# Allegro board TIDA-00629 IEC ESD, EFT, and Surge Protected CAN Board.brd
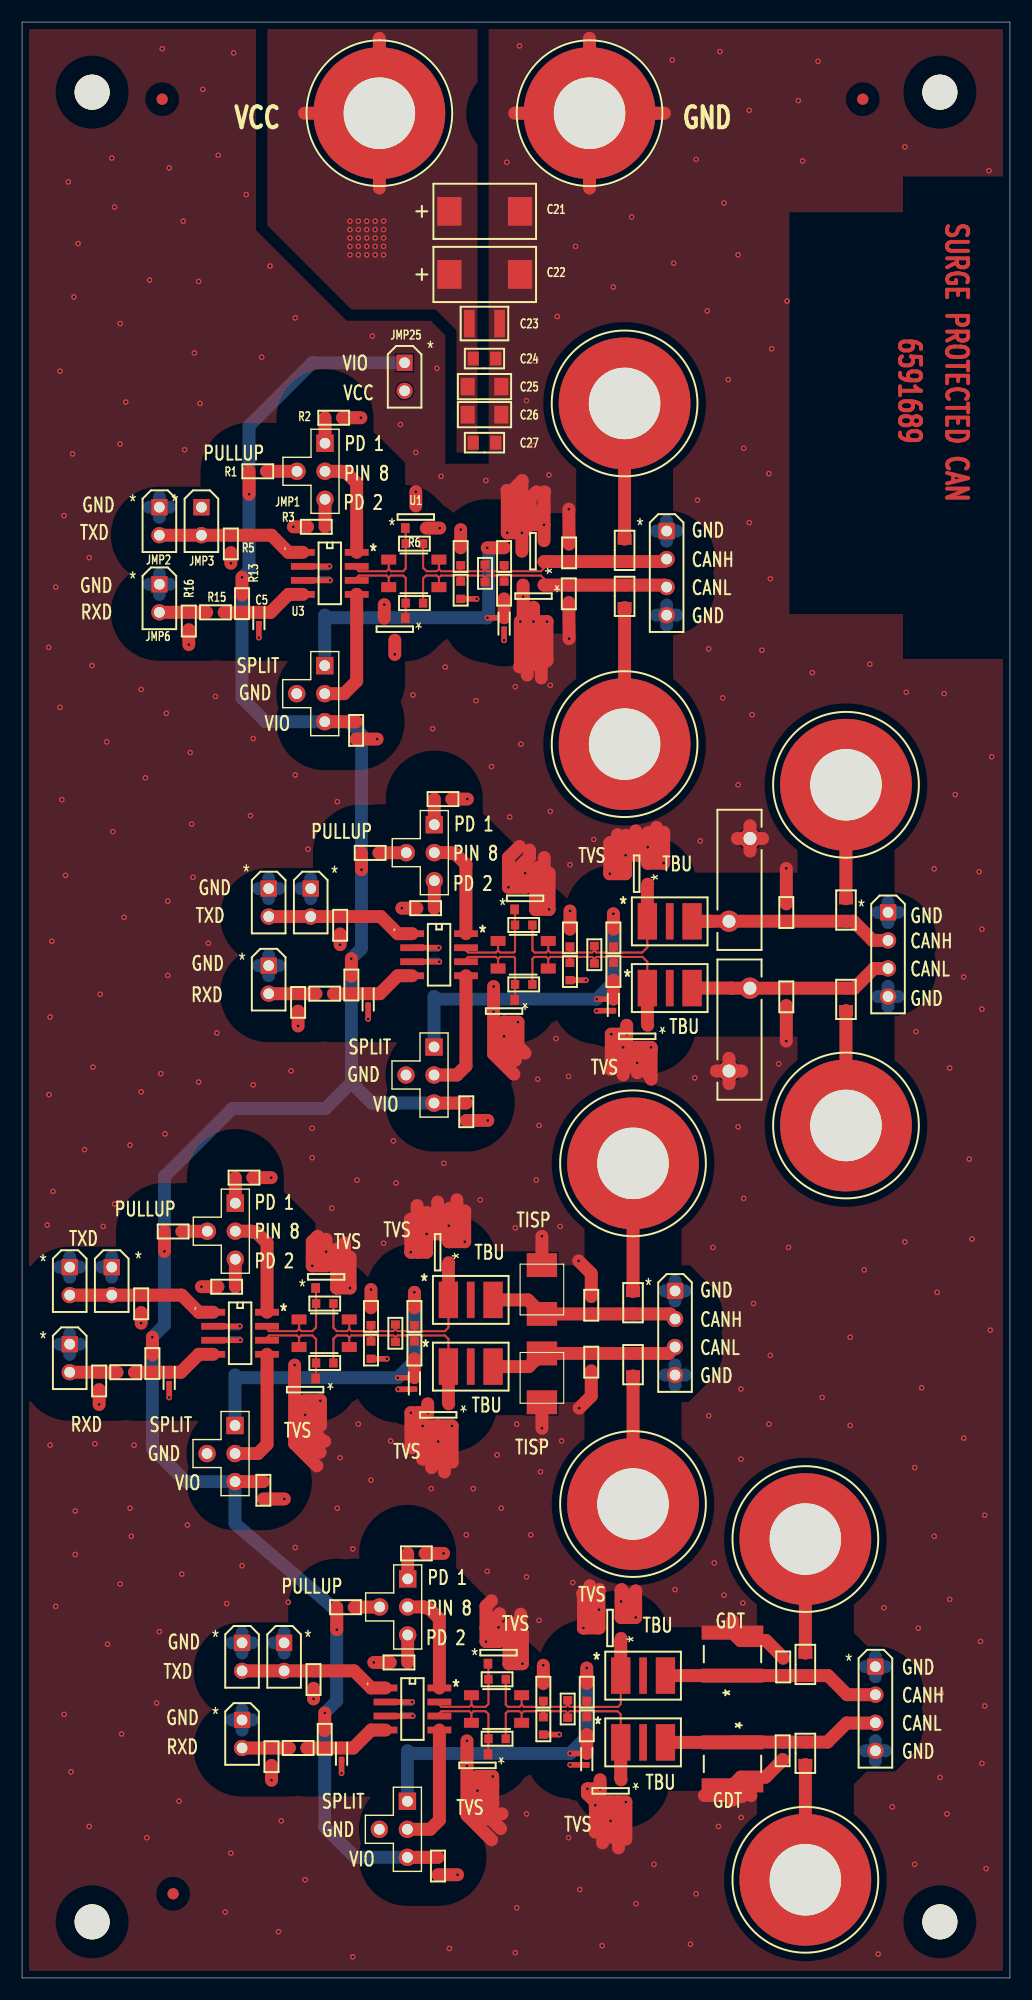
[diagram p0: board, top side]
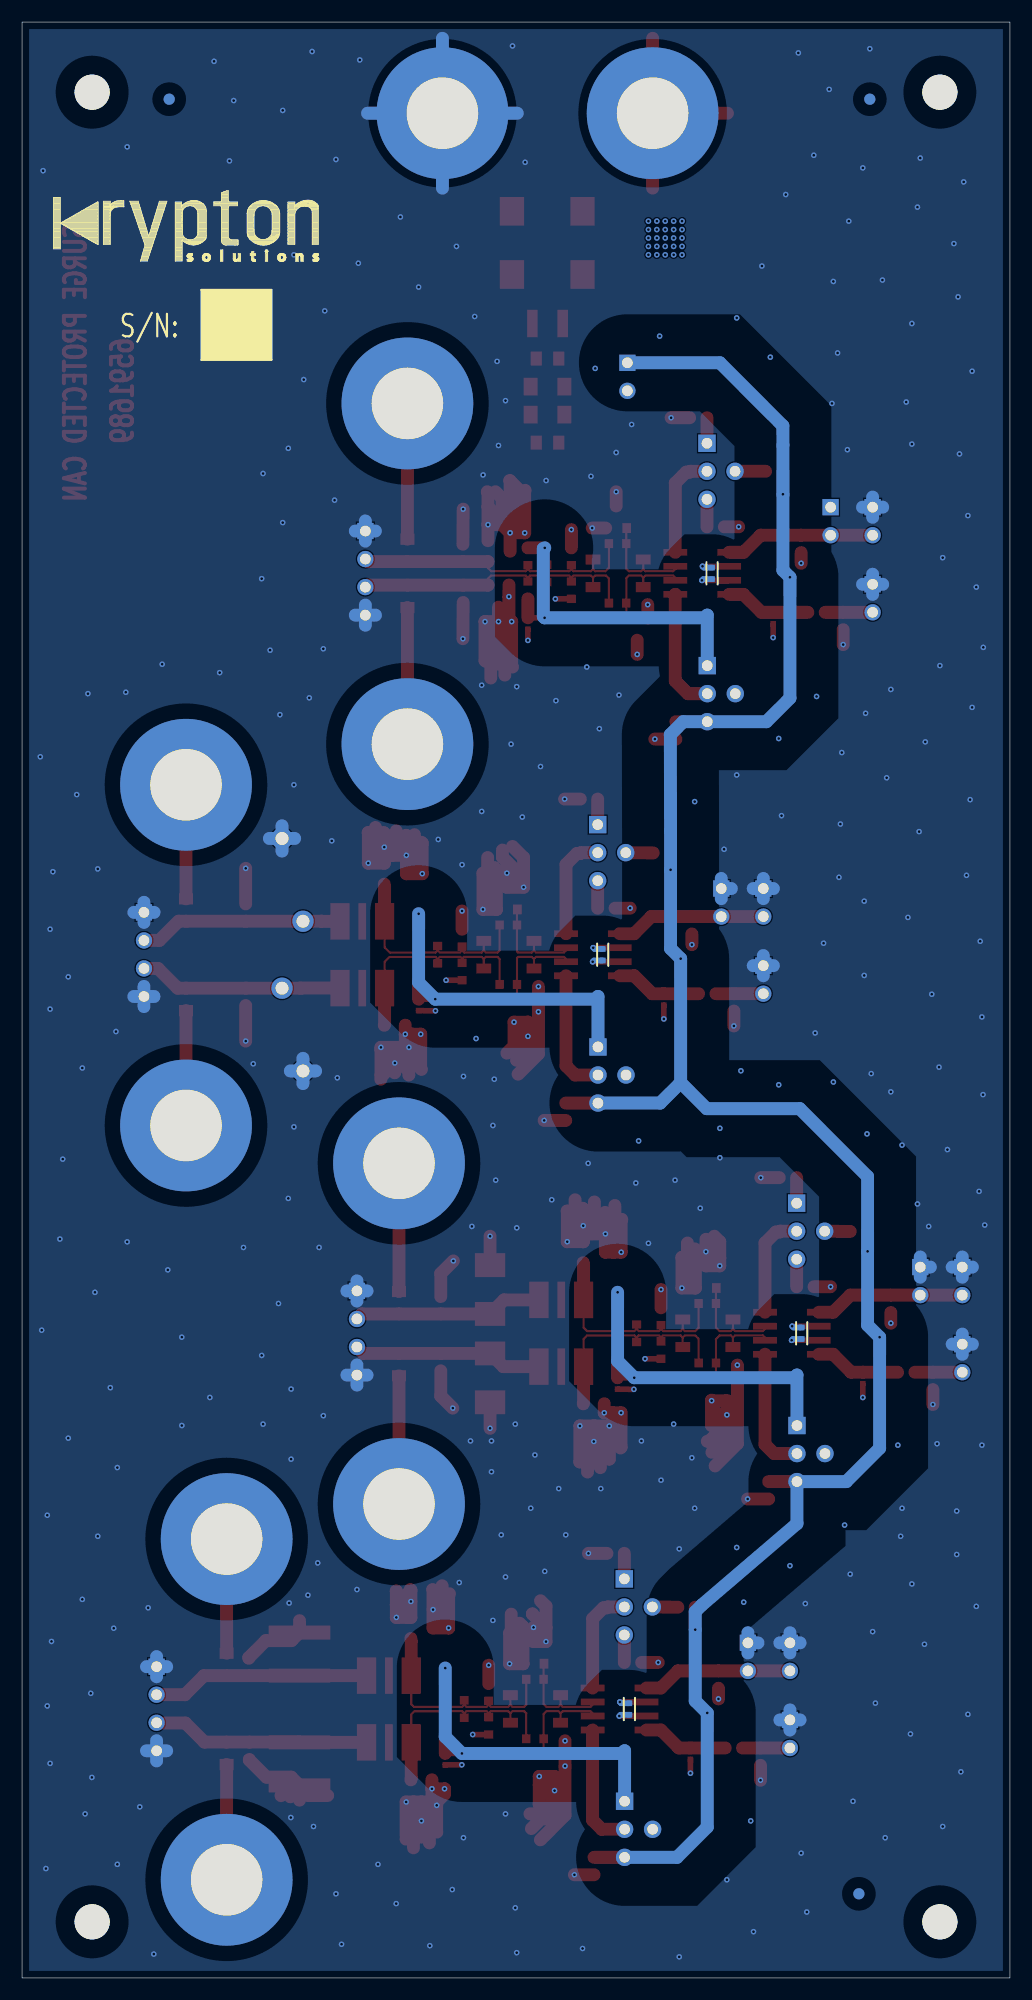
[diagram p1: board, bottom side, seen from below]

Outline 89.53 x 177.16 mm; copper layers: TOP, L2_GND, L3_PWR, BOTTOM. Coordinates in mm from the lower left corner of the outline.
Outline path: 0,177.16 89.53,177.16 89.53,0 0,0 0,177.16

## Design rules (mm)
net group DIFFPAIR0: nets RXD1 TXD1
net group DIFFPAIR1: nets CANH1 CANL1
net group DIFFPAIR2: nets RXD2 TXD2
net group DIFFPAIR3: nets CANH2 CANL2
net group DIFFPAIR4: nets RXD3 TXD3
net group DIFFPAIR5: nets CANH3 CANL3
net group DIFFPAIR6: nets RXD4 TXD4
net group DIFFPAIR7: nets CANH4 CANL4
net group DIFFPAIR8: nets CANH_4 CANL_4
net group DIFFPAIR9: nets CANH_1 CANL_1
net group DIFFPAIR10: nets CANH_2 CANL_2
net group DIFFPAIR11: nets CANH_3 CANL_3

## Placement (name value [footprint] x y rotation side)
C1  68pF  [0603]  49.58 129.08 90 top
C2  0.1uF  [0402]  27 127.23 90 bottom
C3  4.7nF_DNI  [0402]  43.69 122.68 270 top
C4  68pF  [0603]  49.56 125.37 270 top
C5  15pF_DNI  [0402]  21.46 123.18 270 top
C6  68pF  [0603]  69.27 96.5 90 top
C7  0.1uF  [0402]  36.91 92.68 90 bottom
C8  4.7nF_DNI  [0402]  53.59 88.14 270 top
C9  68pF  [0603]  69.27 88.87 270 top
C10  15pF_DNI  [0402]  31.37 88.63 270 top
C11  68pF  [0603]  51.59 60.93 90 top
C12  0.1uF  [0402]  18.87 58.39 90 bottom
C13  4.7nF_DNI  [0402]  35.56 53.85 270 top
C14  68pF  [0603]  51.59 55.78 270 top
C15  15pF_DNI  [0402]  13.34 54.34 270 top
C16  68pF  [0603]  68.99 28.17 90 top
C17  0.1uF  [0402]  34.49 24.36 90 bottom
C18  4.7nF_DNI  [0402]  51.18 19.81 270 top
C19  15pF_DNI  [0402]  28.96 20.31 270 top
C20  68pF  [0603]  68.94 20.57 270 top
C21  47uF  [7343]  38.73 160.02 0 top
C22  22uF  [7343]  38.73 154.31 0 top
C23  68uF  [1210]  41.91 149.86 0 top
C24  10uF  [0805]  41.91 146.69 0 top
C25  1uF  [1206]  41.91 144.15 0 top
C26  0.1uF  [1206]  41.91 141.6 0 top
C27  0.01uF  [0805]  41.91 139.06 0 top
C28  0.01uF  [0603]  30.28 113 90 top
C29  0.01uF  [0603]  40.26 78.46 90 top
C30  0.01uF  [0603]  21.87 44.17 90 top
C31  0.01uF  [0603]  37.69 10.13 90 top
JMP1  -  [BERG2X3TEE]  27.46 139.01 270 top
JMP2  -  [HDR_THVT_1X2_100]  12.45 133.22 0 top
JMP3  -  [HDR_THVT_1X2_100]  16.26 133.22 0 top
JMP4  -  [HDR_THVT_1X4_100]  58.42 131.06 0 top
JMP5  -  [BERG2X3TEE]  27.43 118.87 270 top
JMP6  -  [HDR_THVT_1X2_100]  12.45 126.24 0 top
JMP7  -  [BERG2X3TEE]  37.36 104.47 270 top
JMP8  -  [HDR_THVT_1X2_100]  22.35 98.68 0 top
JMP9  -  [HDR_THVT_1X2_100]  26.16 98.68 0 top
JMP10  -  [HDR_THVT_1X4_100]  78.49 96.52 0 top
JMP11  -  [BERG2X3TEE]  37.34 84.33 270 top
JMP12  -  [HDR_THVT_1X2_100]  22.35 91.69 0 top
JMP13  -  [BERG2X3TEE]  19.33 70.18 270 top
JMP14  -  [HDR_THVT_1X2_100]  4.32 64.39 0 top
JMP15  -  [HDR_THVT_1X2_100]  8.13 64.39 0 top
JMP16  -  [HDR_THVT_1X4_100]  59.18 62.23 0 top
JMP17  -  [BERG2X3TEE]  19.3 50.04 270 top
JMP18  -  [HDR_THVT_1X2_100]  4.32 57.4 0 top
JMP19  -  [BERG2X3TEE]  34.95 36.14 270 top
JMP20  -  [HDR_THVT_1X2_100]  19.94 30.35 0 top
JMP21  -  [HDR_THVT_1X2_100]  23.75 30.35 0 top
JMP22  -  [HDR_THVT_1X4_100]  77.34 28.19 0 top
JMP23  -  [BERG2X3TEE]  34.92 16 270 top
JMP24  -  [HDR_THVT_1X2_100]  19.94 23.37 0 top
JMP25  2 Pin Berg Jumper  [HDR_THVT_1X2_100]  34.67 146.3 0 top
L1  ACT45B Choke  [IND_ACT45B_SMT_4P5X3P2MM]  35.51 127.23 0 top
L2  ACT45B Choke  [IND_ACT45B_SMT_4P5X3P2MM]  45.42 92.68 0 top
L3  ACT45B Choke  [IND_ACT45B_SMT_4P5X3P2MM]  27.38 58.39 0 top
L4  ACT45B Choke  [IND_ACT45B_SMT_4P5X3P2MM]  43 24.36 0 top
NOREF  -  []  89.53 0 90 top
NOREF#2  -  [unnamed#2]  76.2 170.18 0 top
NOREF#3  -  []  88.9 38.1 0 top
NOREF#4  -  [unnamed#2]  83.19 170.81 0 top
NOREF#5  -  []  70.97 158.14 270 top
NOREF#6  -  [unnamed#2]  12.7 170.18 0 top
NOREF#7  -  [unnamed#2]  6.35 170.81 0 top
NOREF#8  -  [unnamed#2]  83.19 5.08 0 top
NOREF#9  -  []  0 177.16 0 top
NOREF#10  -  []  0 0 0 top
NOREF#11  -  []  -3.81 -69.85 0 top
NOREF#12  -  [unnamed#2]  6.35 5.08 0 top
NOREF#13  -  [unnamed#2]  13.69 7.62 0 top
NOREF#14  -  [unnamed#2]  12.7 170.18 180 bottom
NOREF#15  -  [unnamed#2]  76.2 170.18 180 bottom
NOREF#16  -  []  78.23 137.92 180 bottom
NOREF#17  -  []  86.74 155.45 180 bottom
NOREF#18  -  []  80.26 149.73 180 bottom
NOREF#19  -  [unnamed#2]  13.69 7.62 180 bottom
P1  CANH SURGE INPUT  [JACK_THVT_BANANA_500DIA]  54.61 142.62 0 top
P2  CANL SURGE INPUT  [JACK_THVT_BANANA_500DIA]  54.61 111.76 0 top
P3  CANH SURGE INPUT  [JACK_THVT_BANANA_500DIA]  74.68 108.08 0 top
P4  CANL SURGE INPUT  [JACK_THVT_BANANA_500DIA]  74.68 77.22 0 top
P5  CANH SURGE INPUT  [JACK_THVT_BANANA_500DIA]  55.37 73.79 0 top
P6  CANL SURGE INPUT  [JACK_THVT_BANANA_500DIA]  55.37 42.93 0 top
P7  CANH SURGE INPUT  [JACK_THVT_BANANA_500DIA]  70.99 39.75 0 top
P8  CANL SURGE INPUT  [JACK_THVT_BANANA_500DIA]  70.99 8.89 0 top
P9  GND  [JACK_THVT_BANANA_500DIA]  51.44 168.91 0 top
P10  VCC  [JACK_THVT_BANANA_500DIA]  32.38 168.91 0 top
R1  4.7k  [0603]  21.36 136.47 0 top
R2  0  [0603]  28.24 141.33 0 top
R3  10k  [0603]  26.67 131.44 180 top
R4  0  [0805]  54.61 129.31 270 top
R5  49.9  [0603]  18.92 129.9 270 top
R6  0_DNI  [0603]  35.56 129.92 0 top
R7  49.9_DNI  [0603]  39.75 128.75 90 top
R8  60.4_DNI  [0603]  43.69 128.75 90 top
R9  120  [0603]  41.96 127.23 270 top
R10  0_DNI  [0603]  35.56 124.54 0 top
R11  60.4_DNI  [0603]  43.69 125.7 90 top
R12  49.9_DNI  [0603]  39.75 125.7 270 top
R13  10k_DNI  [0603]  19.94 124.49 90 top
R14  0  [0805]  54.61 125.15 270 top
R15  453  [0603]  17.53 123.7 0 top
R16  49.9  [0603]  15.11 122.91 90 top
R17  4.7k  [0603]  31.55 101.9 0 top
R18  0  [0805]  74.68 96.73 270 top
R19  0  [0603]  38.15 106.78 0 top
R20  10k  [0603]  36.58 96.9 180 top
R21  49.9  [0603]  28.83 95.35 270 top
R22  0_DNI  [0603]  45.47 95.38 0 top
R23  49.9_DNI  [0603]  49.66 94.21 90 top
R24  60_DNI  [0603]  53.59 94.21 90 top
R25  120  [0603]  51.87 92.68 270 top
R26  0_DNI  [0603]  45.47 89.99 0 top
R27  60_DNI  [0603]  53.59 91.16 90 top
R28  49.9_DNI  [0603]  49.66 91.16 270 top
R29  10k_DNI  [0603]  29.84 89.94 90 top
R30  453  [0603]  27.43 89.15 0 top
R31  49.9  [0603]  25.02 88.37 90 top
R32  0  [0805]  74.68 88.64 270 top
R33  4.7k  [0603]  13.69 67.61 0 top
R34  0  [0805]  55.37 61.16 270 top
R35  0  [0603]  20.12 72.49 0 top
R36  10k  [0603]  18.54 62.61 180 top
R37  49.9  [0603]  10.79 61.06 270 top
R38  0_DNI  [0603]  27.43 61.09 0 top
R39  49.9_DNI  [0603]  31.62 59.92 90 top
R40  60_DNI  [0603]  35.56 59.92 90 top
R41  120  [0603]  33.83 58.39 270 top
R42  0_DNI  [0603]  27.43 55.7 0 top
R43  60_DNI  [0603]  35.56 56.87 90 top
R44  49.9_DNI  [0603]  31.62 56.87 270 top
R45  10k_DNI  [0603]  11.81 55.65 90 top
R46  453  [0603]  9.4 54.86 0 top
R47  49.9  [0603]  6.99 54.08 90 top
R48  0  [0805]  55.37 55.55 270 top
R49  4.7k  [0603]  29.31 33.58 0 top
R50  0  [0805]  70.99 28.4 270 top
R51  0  [0603]  35.74 38.46 0 top
R52  10k  [0603]  34.16 28.57 180 top
R53  49.9  [0603]  26.42 27.03 270 top
R54  0_DNI  [0603]  43.05 27.05 0 top
R55  49.9_DNI  [0603]  47.24 25.88 90 top
R56  60_DNI  [0603]  51.18 25.88 90 top
R57  120  [0603]  49.45 24.36 270 top
R58  0_DNI  [0603]  43.05 21.67 0 top
R59  60_DNI  [0603]  51.18 22.83 90 top
R60  49.9_DNI  [0603]  47.24 22.83 270 top
R61  10k_DNI  [0603]  27.43 21.62 90 top
R62  453  [0603]  25.02 20.83 0 top
R63  49.9  [0603]  22.61 20.04 90 top
R64  0  [0805]  70.99 20.35 270 top
U1  T12LC  [SOT_23_321]  35.69 132.33 0 top
U2  T12LC  [SOT_23_321]  46.3 129.24 90 top
U3  SN65HVD1040  [SOIC8_157X197_50]  27.89 127.23 0 top
U4  T12LC  [SOT_23_321]  33.78 122.17 180 top
U5  T12LC  [SOT_23_321]  46.35 125.17 180 top
U6  T12LC  [SOT_23_321]  55.7 100.03 90 top
U7  T12LC  [SOT_23_321]  45.59 97.79 0 top
U8  TBU-CA085-200-WH  [DFN_3_157X256]  58.7 95.71 0 top
U9  MOV-10D201K  [VAR_DISC_3P8X12P5MM]  65.02 99.47 90 top
U10  SN65HVD1040  [SOIC8_157X197_50]  37.8 92.68 0 top
U11  MOV-10D201K  [VAR_DISC_3P8X12P5MM]  65.02 85.9 90 top
U12  T12LC  [SOT_23_321]  43.69 87.58 180 top
U13  TBU-CA085-200-WH  [DFN_3_157X256]  58.7 89.66 0 top
U14  T12LC  [SOT_23_321]  55.75 85.29 180 top
U15  T12LC  [SOT_23_321]  37.67 65.74 90 top
U16  T12LC  [SOT_23_321]  27.56 63.5 0 top
U17  TBU-CA085-200-WH  [DFN_3_157X256]  40.67 61.42 0 top
U18  TISP4240M3BJR-S  [DO-214AA]  47.12 62.36 90 top
U19  SN65HVD1040  [SOIC8_157X197_50]  19.76 58.39 0 top
U20  TISP4240M3BJR-S  [DO-214AA]  47.12 54.36 90 top
U21  TBU-CA085-200-WH  [DFN_3_157X256]  40.67 55.37 0 top
U22  T12LC  [SOT_23_321]  25.65 53.29 180 top
U23  T12LC  [SOT_23_321]  37.72 51 180 top
U24  T12LC  [SOT_23_321]  53.29 31.7 90 top
U25  TBU-CA085-200-WH  [DFN_3_157X256]  56.29 27.38 0 top
U26  T12LC  [SOT_23_321]  43.18 29.46 0 top
U27  2031-42T-SM-RPLF  [GDT_SM_2031-XXT]  64.39 29.33 90 top
U28  SN65HVD1040  [SOIC8_157X197_50]  35.38 24.36 0 top
U29  2031-42T-SM-RPLF  [GDT_SM_2031-XXT]  64.39 19.39 270 top
U30  T12LC  [SOT_23_321]  41.27 19.25 180 top
U31  TBU-CA085-200-WH  [DFN_3_157X256]  56.29 21.34 0 top
U32  T12LC  [SOT_23_321]  53.34 16.94 180 top

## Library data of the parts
C1 C4 C6 C9 C11 C14 C16 C20 C24 = CAP NP
C2 C3 C5 C7 C8 C10 C12 C13 C15 C17-C19 C28-C31 = cc0402
C21 C22 = c7343
C23 C25 = NPCap1206_1.0uf
C26 = NPCap1206_0.1uf
C27 = NPCap0805_0.01uf
JMP1 JMP5 JMP7 JMP11 JMP13 JMP17 JMP19 JMP23 = 4 Pin-T Berg Jumper
JMP2 JMP3 JMP6 JMP8 JMP9 JMP12 JMP14 JMP15 JMP18 JMP20 JMP21 JMP24 JMP25 = 2 Pin Berg Jumper
JMP4 JMP10 JMP16 JMP22 = 4 Pin Berg Jumper Stagard Side
L1-L4 = ACT45B Choke
P1-P10 = Banana-Jack
R1-R64 = r0603
U1 U2 U4-U7 U12 U14-U16 U22-U24 U26 U30 U32 = CDSOT23-T12LC_0
U3 U10 U19 U28 = SN65HVD1040
U8 U13 U17 U21 U25 U31 = TBU-CA085-200-WH_0
U9 U11 = MOV-10D201K
U18 U20 = TISP4240M3BJR-S
U27 U29 = 2031-42T-SM-RPLF

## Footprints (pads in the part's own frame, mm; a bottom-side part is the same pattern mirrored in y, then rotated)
0402
  rect 0.508x0.508 smd: 1(-0.521,0) 2(0.521,0)
0603
  rect 0.762x0.813 smd: 1(-0.787,0) 2(0.787,0)
0805
  rect 1.016x1.27 smd: 1(-1.016,0) 2(1.016,0)
1206
  rect 1.27x1.6 smd: 1(-1.524,0) 2(1.524,0)
1210
  rect 0.965x2.489 smd: 1(-1.372,0) 2(1.372,0)
7343
  rect 2.2x2.601 smd: 1(0,0) 2(6.4,0)
BERG2X3TEE
  rect 1.575x1.575 hole 0.965: 1(0,0)
  round 1.575 hole 0.965: 2(2.54,0) 3(5.08,0) 4(2.54,-2.54)
DFN_3_157X256
  rect 1.75x3.3 smd: 1(-2.025,0) 3(2.025,0)
  rect 0.7x3.3 smd: 2(0,0)
DO-214AA
  rect 2.16x2.75 smd: 1(-2.21,0) 2(2.21,0)
GDT_SM_2031-XXT
  rect 1.27x5.588 smd: 1(-1.95,0) 2(1.95,0)
HDR_THVT_1X2_100
  rect 1.473x1.473 hole 0.965: 1(0,0)
  round 1.473 hole 0.965: 2(0,-2.54)
HDR_THVT_1X4_100
  rect 1.473x1.473 hole 0.965: 1(0,0)
  round 1.473 hole 0.965: 2(0,-2.54) 3(0,-5.08) 4(0,-7.62)
IND_ACT45B_SMT_4P5X3P2MM
  rect 1.35x0.9 smd: 1(-2.275,1.25) 2(-2.275,-1.25) 3(2.275,-1.25) 4(2.275,1.25)
JACK_THVT_BANANA_500DIA
  round 11.938 hole 6.477: 1(0,0)
SOIC8_157X197_50
  rect 2.159x0.61 smd: 1(-2.44,1.905) 2(-2.44,0.635) 3(-2.44,-0.635) 4(-2.44,-1.905) 5(2.44,-1.905) 6(2.44,-0.635) 7(2.44,0.635) 8(2.44,1.905)
SOT_23_321
  rect 0.787x0.889 smd: 1(-0.953,-1.003) 2(0.953,-1.003) 3(0,1.003)
unnamed#2
  round 1.016 smd: (0,0)
VAR_DISC_3P8X12P5MM
  round 1.93 hole 1.168: 1(-3.75,0.95) 2(3.75,-0.95)

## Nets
GND: C1.2 C2.2 C3.2 C4.2 C5.2 C6.2 C7.2 C8.2 C9.2 C10.2 C11.2 C12.2 C13.2 C14.2 C15.2 C16.2 C17.2 C18.2 C19.2 C20.2 C21.2 C22.2 C23.2 C24.2 C25.2 C26.2 C27.2 C28.1 C29.1 C30.1 C31.1 JMP2.1 JMP3.1 JMP4.1 JMP4.4 JMP5.4 JMP6.1 JMP8.1 JMP9.1 JMP10.1 JMP10.4 JMP11.4 JMP12.1 JMP14.1 JMP15.1 JMP16.1 JMP16.4 JMP17.4 JMP18.1 JMP20.1 JMP21.1 JMP22.1 JMP22.4 JMP23.4 JMP24.1 P9.1(V) R2.2 R3.2 R5.2 R7.2 R12.2 R16.1 R19.2 R20.2 R21.2 R23.2 R28.2 R31.1 R35.2 R36.2 R37.2 R39.2 R44.2 R47.1 R51.2 R52.2 R53.2 R55.2 R60.2 R63.1 U1.2(GND2) U1.3(GND1) U2.2(GND2) U2.3(GND1) U3.2(GND) U4.2(GND2) U4.3(GND1) U5.2(GND2) U5.3(GND1) U6.2(GND2) U6.3(GND1) U7.2(GND2) U7.3(GND1) U9.2 U10.2(GND) U11.1 U12.2(GND2) U12.3(GND1) U14.2(GND2) U14.3(GND1) U15.2(GND2) U15.3(GND1) U16.2(GND2) U16.3(GND1) U18.2(GND) U19.2(GND) U20.1(SIGNAL) U22.2(GND2) U22.3(GND1) U23.2(GND2) U23.3(GND1) U24.2(GND2) U24.3(GND1) U26.2(GND2) U26.3(GND1) U27.2(IN2) U28.2(GND) U29.2(IN2) U30.2(GND2) U30.3(GND1) U32.2(GND2) U32.3(GND1)
VCC: C2.1 C7.1 C12.1 C17.1 C21.1 C22.1 C23.1 C24.1 C25.1 C26.1 C27.1 JMP25.2 P10.1(V) U3.3(VCC) U10.3(VCC) U19.3(VCC) U28.3(VCC)
CANH1: L1.1 R6.1 U1.1(SIG) U3.7(CANH)
CANH2: L2.1 R22.1 U7.1(SIG) U10.7(CANH)
CANH3: L3.1 R38.1 U16.1(SIG) U19.7(CANH)
CANH4: L4.1 R54.1 U26.1(SIG) U28.7(CANH)
CANH_1: C1.1 JMP4.2 L1.4 R4.2 R6.2 R7.1 R8.1 R9.1 U2.1(SIG)
CANH_2: L2.4 R22.2 R23.1 R24.1 R25.1 U6.1(SIG) U8.1(IN)
CANH_2A: C6.1 JMP10.2 R18.2 U8.3(OUT1) U9.1
CANH_3: L3.4 R38.2 R39.1 R40.1 R41.1 U15.1(SIG) U17.1(IN)
CANH_3A: C11.1 JMP16.2 R34.2 U17.3(OUT1) U18.1(SIGNAL)
CANH_4: L4.4 R54.2 R55.1 R56.1 R57.1 U24.1(SIG) U25.1(IN)
CANH_4A: C16.1 JMP22.2 R50.2 U25.3(OUT1) U27.1(IN1)
CANH_SURGE1: P1.1(V) R4.1
CANH_SURGE2: P3.1(V) R18.1
CANH_SURGE3: P5.1(V) R34.1
CANH_SURGE4: P7.1(V) R50.1
CANL1: L1.2 R10.1 U3.6(CANL) U4.1(SIG)
CANL2: L2.2 R26.1 U10.6(CANL) U12.1(SIG)
CANL3: L3.2 R42.1 U19.6(CANL) U22.1(SIG)
CANL4: L4.2 R58.1 U28.6(CANL) U30.1(SIG)
CANL_1: C4.1 JMP4.3 L1.3 R9.2 R10.2 R11.2 R12.1 R14.1 U5.1(SIG)
CANL_2: L2.3 R25.2 R26.2 R27.2 R28.1 U13.1(IN) U14.1(SIG)
CANL_2A: C9.1 JMP10.3 R32.1 U11.2 U13.3(OUT1)
CANL_3: L3.3 R41.2 R42.2 R43.2 R44.1 U21.1(IN) U23.1(SIG)
CANL_3A: C14.1 JMP16.3 R48.1 U20.2(GND) U21.3(OUT1)
CANL_4: L4.3 R57.2 R58.2 R59.2 R60.1 U31.1(IN) U32.1(SIG)
CANL_4A: C20.1 JMP22.3 R64.1 U29.1(IN1) U31.3(OUT1)
CANL_SURGE1: P2.1(V) R14.2
CANL_SURGE2: P4.1(V) R32.2
CANL_SURGE3: P6.1(V) R48.2
CANL_SURGE4: P8.1(V) R64.2
PD1: JMP1.1 R2.1
PD2: JMP7.1 R19.1
PD3: JMP13.1 R35.1
PD4: JMP19.1 R51.1
PD_SC1: JMP1.3 R3.1
PD_SC2: JMP7.3 R20.1
PD_SC3: JMP13.3 R36.1
PD_SC4: JMP19.3 R52.1
PU1: JMP1.4 R1.2
PU2: JMP7.4 R17.2
PU3: JMP13.4 R33.2
PU4: JMP19.4 R49.2
RXD1: C5.1 R13.1 R15.2 U3.4(RXD)
RXD2: C10.1 R29.1 R30.2 U10.4(RXD)
RXD3: C15.1 R45.1 R46.2 U19.4(RXD)
RXD4: C19.1 R61.1 R62.2 U28.4(RXD)
RXD_SD1: JMP6.2 R15.1 R16.2
RXD_SD2: JMP12.2 R30.1 R31.2
RXD_SD3: JMP18.2 R46.1 R47.2
RXD_SD4: JMP24.2 R62.1 R63.2
SPLIT1: C3.1 JMP5.1 R8.2 R11.1
SPLIT2: C8.1 JMP11.1 R24.2 R27.1
SPLIT3: C13.1 JMP17.1 R40.2 R43.1
SPLIT4: C18.1 JMP23.1 R56.2 R59.1
SPLIT/VIO1: JMP5.2 U3.5(SPLIT)
SPLIT/VIO2: JMP11.2 U10.5(SPLIT)
SPLIT/VIO3: JMP17.2 U19.5(SPLIT)
SPLIT/VIO4: JMP23.2 U28.5(SPLIT)
STB1: JMP1.2 U3.8(STB)
STB2: JMP7.2 U10.8(STB)
STB3: JMP13.2 U19.8(STB)
STB4: JMP19.2 U28.8(STB)
TXD1: JMP2.2 JMP3.2 R5.1 U3.1(TXD)
TXD2: JMP8.2 JMP9.2 R21.1 U10.1(TXD)
TXD3: JMP14.2 JMP15.2 R37.1 U19.1(TXD)
TXD4: JMP20.2 JMP21.2 R53.1 U28.1(TXD)
VIO: C28.2 C29.2 C30.2 C31.2 JMP5.3 JMP11.3 JMP17.3 JMP23.3 JMP25.1 R1.1 R13.2 R17.1 R29.2 R33.1 R45.2 R49.1 R61.2

Pads without a net: U8 2; U13 2; U17 2; U21 2; U25 2; U31 2

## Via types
v1: diameter 0.508, hole 0.254, TOP to BOTTOM, 410 vias

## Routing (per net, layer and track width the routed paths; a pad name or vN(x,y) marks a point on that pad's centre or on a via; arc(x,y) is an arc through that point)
GND: length 726.5
  TOP w0.508: C3.2 v1(43.69,121.16) ; U19.2 v1(19.74,59.03) ; C13.2 v1(34.09,53.31) ; U3.2 v1(27.86,127.86) ; C19.2 v1(28.96,18.54) ; C15.2 v1(13.34,52.58) ; R28.2 v1(51.1,90.37) ; U28.2 v1(35.36,24.99) ; C8.2 v1(52.07,87.6) ; C10.2 v1(31.37,86.87) ; U10.2 v1(37.77,93.32) ; C18.2 v1(49.68,19.3) ; R12.2 v1(41.2,124.92) ; C5.2 v1(21.46,121.41) ; R44.2 v1(33.07,56.08) ; R60.2 v1(48.69,22.05)
  TOP w1.168: 45.21,31.37 45.35,31.23 v1(45.35,28.46) U26.2 ; 55.61,33.79 v1(55.61,32.65) 54.47,32.65 ; 55.61,33.79 55.61,35.04 55.63,35.05 ; 55.61,33.79 54.47,32.65 ; 55.61,33.79 54.29,35.12 ; 46.04,131.64 46.04,131.98 ; 46.04,131.64 v1(47.31,131.64) ; 46.04,131.64 v1(45.3,130.9) ; 46.04,131.98 46.04,134.02 46.63,134.62 ; 46.04,131.98 47.31,133.25 ; 45.59,99.05 v1(45.59,100.08) 45.59,101.09 ; 45.59,99.05 U7.3 v1(44.08,98.79) 44.08,99.6 ; 45.59,99.05 44.57,100.08 ; v1(24.7,55.51) U22.2 24.7,48.4 26.72,46.38 ; v1(50.88,31.7) U24.3 v1(52.29,33.36) 52.29,35.14 52.32,35.18 ; v1(50.88,31.7) 51.46,32.29 51.46,35.52 ; v1(50.88,31.7) 50.88,34.72 50.8,34.8 ; R63.1 v1(22.61,17.91) ; U26.2 45.2,29.53 45.2,32.95 ; U26.2 44.13,31.81 44.45,32.13 ; 62.93,82.15 U11.1 ; U11.1 65.22,82.15 ; U11.1 64.07,83.3 ; U11.1 64.07,81.01 ; v1(45.16,122.86) 45.42,123.11 v1(45.42,125.12) U5.2 ; v1(45.16,122.86) v1(46.35,122.86) ; v1(45.16,122.86) 45.16,118.82 45.09,118.75 ; 53.97,103.56 53.97,100.76 U6.3 ; 27.43,48.61 27.27,48.61 25.65,50.22 ; 40.13,69.47 40.12,69.46 v1(40.12,66.69) U15.2 ; 25.65,50.22 25.65,48.97 27.01,47.61 ; 25.65,50.22 v1(25.65,51) U22.3 v1(27.04,52.29) ; 25.65,50.22 27.04,51.61 ; 55.97,101.69 55.62,102.04 55.62,103.9 ; 55.97,101.69 v1(54.7,101.69) ; 55.97,101.69 v1(56.71,102.43) ; 38.73,69.72 38.67,69.66 v1(38.67,68.14) ; 53.34,12.75 v1(53.34,14.22) U32.3 ; 42.66,17.49 v1(42.66,18.25) 41.94,18.25 ; 42.66,17.49 42.66,15.76 ; 42.66,17.49 42.27,17.1 ; v1(46.35,122.86) v1(47.57,122.86) ; v1(46.35,122.86) 45.78,122.29 45.78,118.02 ; v1(46.35,122.86) 46.35,119 ; v1(46.35,122.86) U5.3 ; v1(47.57,122.86) 47.05,122.34 47.05,117.75 ; v1(47.57,122.86) 47.57,119.33 47.5,119.25 ; 52.64,15.94 51.96,15.94 ; 52.64,15.94 52.39,16.19 v1(52.39,17.13) ; 52.64,15.94 U32.3 ; 52.64,15.94 52.62,15.91 52.62,12.23 ; 51.96,15.94 v1(51.96,15.63) 51.96,13.53 ; 51.96,15.94 51.24,16.65 v1(51.24,17.13) v1(52.39,17.13) ; 42.55,34.16 42.05,33.67 42.05,31.73 ; 58.17,103.76 58.15,103.75 v1(58.15,100.98) U6.2 ; U32.3 54.03,15.94 ; 42.05,31.73 v1(42.05,30.47) U26.3 v1(43.18,31.75) ; 42.05,31.73 43.28,32.96 43.28,32.98 ; C29.1 v1(42.21,77.67) ; v1(56.71,102.43) 56.71,103.7 56.77,103.76 ; v1(56.71,102.43) U6.2 ; C9.2 v1(69.27,84.86) ; U6.2 57.5,101.78 57.5,104.22 ; v1(52.39,17.13) U32.2 ; R37.2 v1(10.79,59.31) ; U23.2 v1(36.77,51.19) 36.01,51.19 ; 27.55,66.91 27.55,66.46 26.3,65.21 ; 64.83,103.22 U9.2 ; U9.2 65.97,104.36 ; U9.2 67.12,103.22 ; U9.2 65.97,102.07 ; v1(45.3,130.9) 45.3,135.6 ; v1(45.3,130.9) 45.15,130.9 ; v1(45.3,130.9) U2.3 ; 45.3,135.6 44.32,134.62 44.32,131.73 45.15,130.9 ; 45.3,135.6 45.34,135.64 ; U29.2 65.14,17.44 66.07,16.51 ; U29.2 65.14,18.19 67.39,18.19 68.94,19.74 C20.2 ; U29.2 64.39,17.35 ; v1(40.32,21.48) U30.2 v1(40.32,19.19) 40.32,14.74 42.56,12.51 ; v1(55.75,82.88) 55.75,81.99 ; v1(55.75,82.88) 55.75,83.41 ; v1(55.75,82.88) 56.88,81.75 57.01,81.75 57.01,84.14 ; v1(55.75,82.88) 57.01,84.14 ; v1(69.27,100.51) C6.2 ; 55.75,83.41 54.47,82.13 v1(54.47,84.29) ; 55.75,83.41 U14.3 ; 55.75,83.41 54.88,84.29 ; v1(54.8,85.48) 54.16,85.48 ; v1(54.8,85.48) 54.8,84.37 54.88,84.29 ; v1(54.8,85.48) U14.2 ; 54.16,85.48 v1(53.4,85.48) 53.4,82.69 ; 54.16,85.48 54.16,84.6 v1(54.47,84.29) ; 44.08,99.6 44.08,101.49 45.09,102.49 ; 44.08,99.6 44.57,100.08 ; R51.2 v1(38.2,38.46) ; 41.94,18.25 U30.3 v1(41.27,16.97) 41.27,16.11 ; 41.94,18.25 41.94,17.43 42.27,17.1 ; 29.23,66.57 29.23,63.21 U16.2 ; 35.31,48.01 35.24,48.07 v1(35.24,51.19) 36.01,51.19 ; 54.29,35.12 v1(54.29,34.1) U24.2 54.47,32.65 ; 54.29,35.12 54.36,35.18 ; U6.3 v1(53.26,100.03) 53.26,102.79 53.34,102.87 ; U6.3 v1(54.7,101.69) ; 27.05,50.04 27.04,50.05 27.04,51.61 ; v1(36.66,67.4) U15.3 35.94,65.74 ; v1(36.66,67.4) 37.93,67.4 38.25,67.71 ; v1(36.66,67.4) 36.66,69.3 36.7,69.34 ; U4.3 v1(33.78,119.89) ; 54.03,15.94 v1(54.72,15.94) 54.72,12.89 ; 54.03,15.94 54.06,15.91 54.06,11.78 ; U18.2 v1(47.12,67.18) ; R55.2 v1(47.24,28.32) ; U23.3 v1(38.98,50) 38.98,46.75 38.99,46.74 ; U23.3 v1(36.31,50) ; U23.3 v1(37.72,48.59) 37.72,47.19 ; U23.3 38.29,49.43 38.29,45.82 ; v1(54.47,84.29) 54.88,84.29 ; U12.3 v1(44.95,86.58) 44.95,84.42 45.59,83.77 ; U12.3 v1(43.69,85.29) 43.69,84.15 44.7,83.13 44.7,85.56 U12.3 ; 29.72,65.28 29.73,65.27 v1(29.73,62.5) U16.2 ; C16.2 68.99,29.01 67.44,30.56 65.11,30.56 U27.2 64.39,32.36 ; 43.5,14.86 42.52,14.86 41.27,16.11 ; 64.39,17.25 65.23,16.41 ; 64.39,17.25 64.39,16.1 ; 64.39,17.25 64.39,17.35 ; U4.2 v1(32.83,124.4) ; R23.2 v1(49.66,96.65) ; 45.15,130.9 v1(43.98,130.9) 43.98,134.71 43.94,134.75 ; 26.3,65.21 v1(26.3,64.5) U16.3 v1(27.56,65.79) ; 26.3,65.21 26.3,66.69 26.8,67.18 ; v1(54.7,101.69) 54.7,103.47 54.74,103.5 ; C28.1 v1(32.18,112.22) ; R19.2 v1(40.36,106.78) ; R36.2 v1(16.26,62.61) ; R7.2 v1(39.75,131.19) ; 54.74,12.57 54.72,12.59 ; 44.58,81.86 42.74,83.71 v1(42.74,87.52) U12.2 v1(42.74,89.8) ; R16.1 v1(15.11,120.78) ; R3.2 v1(24.59,131.44) ; 36.01,51.19 36.01,50.3 v1(36.31,50) ; R35.2 v1(22.58,72.49) ; C31.1 v1(39.47,9.35) ; U1.3 v1(35.69,134.62) ; 51.94,13.21 51.96,13.22 ; U14.3 54.88,84.29 ; U14.3 v1(57.01,84.29) 57.01,84.14 ; v1(27.04,52.29) 27.04,52.34 ; v1(27.04,52.29) 27.04,51.61 ; 42.27,17.1 41.27,16.11 ; 41.27,16.11 41.27,15.26 42.12,14.41 42.49,14.41 43.37,13.53 ; 42.66,15.76 42.66,15.71 ; 42.66,15.76 42.67,15.75 ; v1(47.31,131.64) 47.31,133.25 ; v1(47.31,131.64) U2.2 ; 47.31,133.25 47.31,134.56 47.37,134.62 ; v1(36.31,50) 37.12,49.19 37.12,46.22 ; v1(36.31,50) 36.31,47 36.32,46.99 ; C30.1 v1(23.77,43.38) ; C11.2 51.59,63.8 v1(50.44,64.95) ; 47.33,101.49 47.33,97.57 U7.2 ; 53.34,82.3 53.4,82.36 ; U16.2 28.51,65.98 28.57,66.04 ; 38.25,67.71 v1(38.67,68.14) ; 38.25,67.71 37.66,68.3 37.66,70.29 ; v1(38.67,68.14) U15.2 ; 54.48,81.79 54.47,81.8 ; 44.57,100.08 45.99,101.51 45.99,102.16 ; v1(50.5,51.61) 51.59,52.7 C14.2 ; R2.2 v1(30.71,141.33) ; 35.18,68.71 35.23,68.66 v1(35.23,65.74) 35.94,65.74 ; 35.94,65.74 35.81,65.87 35.81,69.97 ; U15.2 39.41,67.43 39.41,70.48 ; R21.2 v1(28.83,93.6) ; U7.2 46.55,100.39 46.74,100.58 ; U7.2 v1(47.76,96.79) 47.76,100.06 47.75,100.08 ; 51.44,162.13 P9.1 ; P9.1 44.65,168.91 ; P9.1 51.44,175.69 ; P9.1 58.22,168.91 ; 61.84,16.52 63.56,16.52 64.39,17.35 ; R53.2 v1(26.42,25.27) ; 49.56,124.59 v1(49.58,121.31) ; U20.1 v1(47.12,49.78) ; C1.2 v1(49.56,133.05) ; R47.1 v1(6.99,51.94) ; R20.2 v1(34.42,96.9) ; R5.2 v1(18.92,128.14) ; U1.2 v1(37.86,131.33) ; R52.2 v1(31.88,28.57) ; R39.2 v1(31.62,62.36) ; R31.1 v1(25.02,86.23) ; 57.02,81.41 57.01,81.42
  L2_GND w1.168: 19.94,22.45 JMP24.1 ; JMP24.1 20.85,23.37 ; JMP24.1 19.02,23.37 ; JMP24.1 19.94,24.28 ; JMP20.1 20.85,30.35 ; JMP20.1 19.94,31.27 ; JMP20.1 19.02,30.35 ; JMP20.1 19.94,29.44 ; JMP15.1 9.04,64.39 ; JMP15.1 8.13,63.47 ; JMP15.1 7.21,64.39 ; JMP15.1 8.13,65.3 ; 16.76,46.53 JMP17.4 ; JMP17.4 17.73,47.5 ; JMP17.4 15.8,47.5 ; JMP17.4 16.76,48.46 ; JMP22.4 78.26,20.57 ; JMP22.4 77.34,21.49 ; JMP22.4 76.43,20.57 ; JMP22.4 77.34,19.66 ; JMP3.1 17.17,133.22 ; JMP3.1 16.26,134.14 ; JMP3.1 15.34,133.22 ; JMP3.1 16.26,132.31 ; 64.83,103.22 U9.2 ; U9.2 65.97,102.07 ; U9.2 65.97,104.36 ; U9.2 67.12,103.22 ; JMP4.1 58.42,131.98 ; JMP4.1 58.42,130.15 ; JMP4.1 59.33,131.06 ; JMP4.1 57.51,131.06 ; 22.35,97.76 JMP8.1 ; JMP8.1 22.35,99.59 ; JMP8.1 21.44,98.68 ; JMP8.1 23.27,98.68 ; JMP11.4 35.76,81.79 ; JMP11.4 33.83,81.79 ; JMP11.4 34.8,82.75 ; JMP11.4 34.8,80.82 ; JMP16.4 60.1,54.61 ; JMP16.4 59.18,55.52 ; JMP16.4 59.18,53.7 ; JMP16.4 58.27,54.61 ; 21.44,91.69 JMP12.1 ; JMP12.1 22.35,90.78 ; JMP12.1 23.27,91.69 ; JMP12.1 22.35,92.61 ; 57.51,123.44 JMP4.4 ; JMP4.4 58.42,122.53 ; JMP4.4 59.33,123.44 ; JMP4.4 58.42,124.36 ; 24.89,115.37 JMP5.4 ; JMP5.4 24.89,117.3 ; JMP5.4 25.86,116.33 ; JMP5.4 23.93,116.33 ; JMP10.1 79.4,96.52 ; JMP10.1 78.49,97.43 ; JMP10.1 77.57,96.52 ; JMP10.1 78.49,95.61 ; JMP6.1 13.36,126.24 ; JMP6.1 11.53,126.24 ; JMP6.1 12.45,127.15 ; JMP6.1 12.45,125.32 ; JMP16.1 59.18,63.14 ; JMP16.1 60.1,62.23 ; JMP16.1 59.18,61.32 ; JMP16.1 58.27,62.23 ; JMP18.1 4.32,58.32 ; JMP18.1 3.4,57.4 ; JMP18.1 4.32,56.49 ; JMP18.1 5.23,57.4 ; JMP9.1 26.16,99.59 ; JMP9.1 26.16,97.76 ; JMP9.1 25.25,98.68 ; JMP9.1 27.08,98.68 ; 32.38,12.5 JMP23.4 ; JMP23.4 31.42,13.46 ; JMP23.4 33.35,13.46 ; JMP23.4 32.38,14.43 ; JMP22.1 77.34,29.11 ; JMP22.1 76.43,28.19 ; JMP22.1 78.26,28.19 ; JMP22.1 77.34,27.28 ; U11.1 64.07,83.3 ; U11.1 64.07,81.01 ; U11.1 65.22,82.15 ; U11.1 62.93,82.15 ; 22.83,30.35 JMP21.1 ; JMP21.1 23.75,29.44 ; JMP21.1 23.75,31.27 ; JMP21.1 24.66,30.35 ; 77.57,88.9 JMP10.4 ; JMP10.4 78.49,87.99 ; JMP10.4 79.4,88.9 ; JMP10.4 78.49,89.81 ; JMP2.1 12.45,134.14 ; JMP2.1 11.53,133.22 ; JMP2.1 13.36,133.22 ; JMP2.1 12.45,132.31 ; 4.32,63.47 JMP14.1 ; JMP14.1 3.4,64.39 ; JMP14.1 4.32,65.3 ; JMP14.1 5.23,64.39 ; P9.1 51.44,175.69 ; P9.1 51.44,162.13 ; P9.1 44.65,168.91 ; P9.1 58.22,168.91
  BOTTOM w0.508: C12.2 19.62,58.92 v1(19.74,59.03) ; C2.2 27.75,127.75 v1(27.86,127.86) ; v1(35.36,24.99) 35.24,24.88 C17.2 ; v1(37.77,93.32) 37.66,93.21 C7.2
  BOTTOM w1.168: 23.75,29.44 JMP21.1 ; JMP21.1 22.83,30.35 ; JMP21.1 23.75,31.27 ; JMP14.1 5.23,64.39 ; JMP14.1 4.32,65.3 ; JMP14.1 4.32,63.47 ; JMP14.1 3.4,64.39 ; U11.1 64.07,83.3 ; U11.1 62.93,82.15 ; U11.1 64.07,81.01 ; U11.1 65.22,82.15 ; 11.53,133.22 JMP2.1 ; JMP2.1 13.36,133.22 ; JMP2.1 12.45,132.31 ; JMP2.1 12.45,134.14 ; JMP10.1 79.4,96.52 ; JMP10.1 78.49,95.61 ; JMP10.1 78.49,97.43 ; JMP10.1 77.57,96.52 ; JMP18.1 5.23,57.4 ; JMP18.1 4.32,56.49 ; JMP18.1 3.4,57.4 ; JMP18.1 4.32,58.32 ; 19.94,22.45 JMP24.1 ; JMP24.1 19.02,23.37 ; JMP24.1 20.85,23.37 ; JMP24.1 19.94,24.28 ; JMP6.1 12.45,127.15 ; JMP6.1 13.36,126.24 ; JMP6.1 11.53,126.24 ; JMP6.1 12.45,125.32 ; 59.18,53.7 JMP16.4 ; JMP16.4 59.18,55.52 ; JMP16.4 60.1,54.61 ; JMP16.4 58.27,54.61 ; JMP12.1 22.35,92.61 ; JMP12.1 21.44,91.69 ; JMP12.1 22.35,90.78 ; JMP12.1 23.27,91.69 ; 58.27,62.23 JMP16.1 ; JMP16.1 60.1,62.23 ; JMP16.1 59.18,61.32 ; JMP16.1 59.18,63.14 ; P9.1 51.44,175.69 ; P9.1 58.22,168.91 ; P9.1 51.44,162.13 ; P9.1 44.65,168.91 ; 57.51,123.44 JMP4.4 ; JMP4.4 58.42,122.53 ; JMP4.4 58.42,124.36 ; JMP4.4 59.33,123.44 ; JMP9.1 26.16,99.59 ; JMP9.1 25.25,98.68 ; JMP9.1 26.16,97.76 ; 19.94,29.44 JMP20.1 ; JMP20.1 19.02,30.35 ; JMP20.1 20.85,30.35 ; JMP20.1 19.94,31.27 ; 76.43,20.57 JMP22.4 ; JMP22.4 78.26,20.57 ; JMP22.4 77.34,19.66 ; JMP22.4 77.34,21.49 ; JMP4.1 58.42,131.98 ; JMP4.1 57.51,131.06 ; JMP4.1 58.42,130.15 ; JMP4.1 59.33,131.06 ; JMP22.1 78.26,28.19 ; JMP22.1 76.43,28.19 ; JMP22.1 77.34,27.28 ; JMP22.1 77.34,29.11 ; 64.83,103.22 U9.2 ; U9.2 65.97,102.07 ; U9.2 67.12,103.22 ; U9.2 65.97,104.36 ; JMP10.4 79.4,88.9 ; JMP10.4 78.49,87.99 ; JMP10.4 77.57,88.9 ; JMP10.4 78.49,89.81 ; JMP8.1 22.35,99.59 ; JMP8.1 23.27,98.68 ; JMP8.1 22.35,97.76 ; JMP8.1 21.44,98.68 ; 8.13,63.47 JMP15.1 ; JMP15.1 7.21,64.39 ; JMP15.1 8.13,65.3
  vias: v1(2.29,68.2) v1(2.41,120.52) v1(2.44,80.01) v1(2.54,87.05) v1(2.54,48.26) v1(2.69,93.9) v1(2.79,71.25) v1(3.05,125.98) v1(3.05,33.66) v1(3.43,145.54) v1(3.43,115.09) v1(3.61,106.73) v1(3.81,132.46) v1(3.81,23.88) v1(3.94,99.87) v1(4.19,162.69) v1(4.45,18.67) v1(4.57,138.05) v1(4.7,152.27) v1(4.83,42.29) v1(4.83,38.35) v1(5.08,157.1) v1(5.66,75.03) v1(6.1,128.65) v1(6.1,13.72) v1(6.35,118.87) v1(6.43,82.5) v1(6.6,48.39) v1(7.09,89.1) v1(7.37,68.07) v1(7.67,111.96) v1(7.75,30.23) v1(8.13,164.85) v1(8.23,103.84) v1(8.38,160.4) v1(8.38,70.1) v1(8.89,149.86) v1(8.89,138.94) v1(8.89,35.69) v1(9.02,22.1) v1(9.25,96.06) v1(9.4,142.75) v1(9.78,75.44) v1(9.78,42.55) v1(9.91,40.01) v1(10.16,48.26) v1(10.79,116.71) v1(10.79,80.26) v1(11.18,108.71) v1(11.3,12.7) v1(11.56,153.8) v1(12.19,24.89) v1(12.45,31.37) v1(12.57,81.92) v1(12.7,174.75) v1(12.95,76.45) v1(13.08,114.55) v1(13.21,97.54) v1(13.21,90.81) v1(13.34,163.96) v1(14.22,16) v1(14.48,36.58) v1(14.61,159.13) v1(14.73,138.43) v1(14.99,41.02) v1(15.24,111) v1(15.37,104.52) v1(15.49,99.69) v1(15.62,147.19) v1(16,153.67) v1(16,81.15) v1(16.13,142.62) v1(16.38,171.07) v1(16.89,93.73) v1(17.53,116.08) v1(17.65,85.6) v1(17.78,165.1) v1(18.41,5.97) v1(18.54,33.91) v1(18.92,11.3) v1(19.18,174.37) v1(19.94,37.34) v1(20.32,161.54) v1(20.7,105.28) v1(20.95,112.27) v1(20.95,80.9) v1(21.72,146.81) v1(22.48,155.07) v1(23.24,4.19) v1(23.5,14.22) v1(24.13,34.04) v1(24.38,82.17) v1(24.77,150.37) v1(24.77,108.97) v1(24.77,38.99) v1(25.65,8.89) v1(25.91,102.23) v1(26.29,76.96) v1(26.29,74.3) v1(28.07,69.72) v1(28.57,106.55) v1(28.57,42.55) v1(28.83,47.12) v1(29.97,38.86) v1(29.97,1.91) v1(30.35,72.26) v1(30.48,50.16) v1(31.62,45.09) v1(31.75,148.72) v1(32.77,66.55) v1(33.4,48.64) v1(33.66,75.82) v1(33.91,72.01) v1(34.29,140.72) v1(35.43,116.2) v1(35.69,138.18) v1(37.08,44.32) v1(37.21,113.16) v1(37.59,145.8) v1(37.97,136.02) v1(38.23,73.79) v1(38.35,118.75) v1(38.73,2.67) v1(40.26,40.13) v1(40.89,44.32) v1(41.15,115.7) v1(41.53,70.48) v1(42.04,135.64) v1(42.16,36.83) v1(42.55,109.73) v1(43.05,47.37) v1(43.43,42.55) v1(43.94,164.47) v1(44.2,105.16) v1(44.7,116.97) v1(44.7,67.94) v1(44.7,2.29) v1(44.83,50.16) v1(44.83,6.35) v1(45.09,175.01) v1(45.21,111.76) v1(45.72,142.88) v1(45.72,36.32) v1(45.72,14.86) v1(46.1,40.13) v1(46.35,138.81) v1(46.48,146.43) v1(46.61,72.26) v1(46.74,81.41) v1(46.86,77.22) v1(46.86,32.38) v1(46.99,48.64) v1(46.99,45.85) v1(47.75,136.14) v1(47.88,117.09) v1(47.88,105.66) v1(48.39,85.09) v1(48.51,150.5) v1(48.77,68.07) v1(48.9,48.64) v1(49.53,81.66) v1(49.53,12.7) v1(49.66,100.84) v1(49.91,35.81) v1(50.16,156.84) v1(50.55,8) v1(51.82,103.12) v1(52.58,2.92) v1(53.59,153.16) v1(55.24,159.51) v1(55.63,6.73) v1(57.28,10.29) v1(58.93,173.74) v1(59.05,155.32) v1(59.18,35.18) v1(60.58,3.05) v1(60.96,81.53) v1(61.09,164.72) v1(61.09,7.62) v1(61.21,133.86) v1(61.47,103) v1(62.1,151) v1(62.23,120.4) v1(62.23,50.93) v1(62.61,66.17) v1(62.74,37.59) v1(63.12,13.72) v1(63.25,174.5) v1(63.5,115.95) v1(63.63,160.78) v1(63.63,34.67) v1(64.01,144.78) v1(64.9,156.08) v1(64.9,108.08) v1(64.9,77.09) v1(65.15,53.34) v1(65.15,46.99) v1(65.18,14.53) v1(65.33,33.96) v1(65.41,138.56) v1(65.41,70.61) v1(65.91,169.16) v1(65.91,131.83) v1(66.17,114.43) v1(66.29,61.09) v1(67.06,120.27) v1(67.69,136.27) v1(67.69,50.16) v1(67.82,126.75) v1(67.82,56.39) v1(67.94,147.57) v1(68.58,82.8) v1(69.34,151.89) v1(69.47,66.17) v1(70.36,170.05) v1(70.74,164.59) v1(71.63,118.24) v1(72.14,173.61) v1(72.52,52.58) v1(75.06,58.04) v1(75.06,50.04) v1(76.33,64.14) v1(76.83,119) v1(77.6,2.16) v1(78.11,33.53) v1(78.87,15.49) v1(80.01,165.86) v1(80.01,66.67) v1(80.14,116.46) v1(80.9,46.23) v1(80.9,10.29) v1(81.03,85.72) v1(81.23,31.67) v1(81.53,53.47) v1(82.68,100.46) v1(82.68,40.01) v1(82.93,62.1) v1(83.21,18.16) v1(83.31,25.78) v1(83.57,116.33) v1(83.82,14.86) v1(84.07,82.42) v1(84.07,34.29) v1(84.58,107.19) v1(85.34,90.68) v1(85.34,48.9) v1(85.85,74.17) v1(86.11,66.93) v1(86.74,100.2) v1(86.87,30.48) v1(87,95) v1(87,87.76) v1(87,19.43) v1(87.25,41.91) v1(87.25,24.64) v1(87.38,9.91) v1(87.63,163.7) v1(87.76,58.67) v1(87.88,110.62)
VCC: length 64.8
  TOP w0.508: U3.3 v1(27.91,126.59) ; U28.3 v1(35.41,23.72) ; U19.3 v1(19.79,57.76) ; U10.3 v1(37.82,92.05)
  TOP w1.168: 32.38,162.13 P10.1 ; P10.1 25.6,168.91 ; P10.1 32.38,175.69
  L3_PWR w1.168: 32.38,162.13 P10.1 ; P10.1 32.38,175.69 ; P10.1 25.6,168.91 ; P10.1 39.17,168.91 ; 34.67,142.85 JMP25.2 ; JMP25.2 34.67,144.68 ; JMP25.2 33.76,143.76 ; JMP25.2 35.59,143.76
  BOTTOM w0.508: C7.1 37.71,92.16 v1(37.82,92.05) ; C17.1 35.29,23.84 v1(35.41,23.72) ; v1(27.91,126.59) 27.8,126.71 C2.1 ; v1(19.79,57.76) 19.67,57.87 C12.1
  vias: v1(29.72,159.13) v1(29.72,158.37) v1(29.72,157.61) v1(29.72,156.84) v1(29.72,156.08) v1(30.48,159.13) v1(30.48,158.37) v1(30.48,157.61) v1(30.48,156.84) v1(30.48,156.08) v1(31.24,159.13) v1(31.24,158.37) v1(31.24,157.61) v1(31.24,156.84) v1(31.24,156.08) v1(32,159.13) v1(32,158.37) v1(32,157.61) v1(32,156.84) v1(32,156.08) v1(32.77,159.13) v1(32.77,158.37) v1(32.77,157.61) v1(32.77,156.84) v1(32.77,156.08)
CANH1: length 9.6
  TOP w0.191: 33.23,127.62 33.04,127.43 30.52,127.43 30.33,127.62 U3.7 ; 33.23,127.62 33.42,127.43 34.54,127.43 34.77,127.65 R6.1 34.77,131.29 U1.1 ; 33.23,127.62 L1.1
CANH2: length 9.7
  TOP w0.191: U7.1 44.68,96.75 R22.1 44.68,92.98 44.58,92.88 43.33,92.88 43.14,93.07 ; 43.14,93.07 L2.1 ; 43.14,93.07 42.95,92.88 40.43,92.88 40.24,93.07 U10.7
CANH3: length 9.5
  TOP w0.191: 25.11,58.78 25.3,58.59 26.31,58.59 26.64,58.92 R38.1 26.64,62.46 U16.1 ; 25.11,58.78 24.92,58.59 22.39,58.59 22.2,58.78 U19.7 ; 25.11,58.78 L3.1
CANH4: length 9.6
  TOP w0.191: 40.73,24.75 40.54,24.56 38.01,24.56 37.82,24.75 U28.7 ; 40.73,24.75 40.92,24.56 42.01,24.56 42.27,24.82 R54.1 42.27,28.42 U26.1 ; 40.73,24.75 L4.1
CANH_1: length 27.8
  TOP w0.191: 41.96,127.62 42.15,127.43 43.5,127.43 43.69,127.62 43.69,127.64 ; 41.96,127.62 R9.1 ; 41.96,127.62 41.77,127.43 39.94,127.43 39.75,127.62 ; 39.75,127.62 39.56,127.43 37.97,127.43 37.78,127.61 37.78,127.62 ; 39.75,127.62 R7.1 ; 43.69,127.64 R8.1 ; 43.69,127.64 43.9,127.43 47.02,127.43 47.31,127.71 U2.1 ; 37.78,127.62 37.59,127.43 36.66,127.43 36.35,127.74 R6.2 ; 37.78,127.62 L1.4
  TOP w1.168: JMP4.2 58.19,128.3 R4.2 C1.1 47.32,128.3 U2.1
CANH_2: length 21.3
  TOP w0.191: 49.66,93.07 49.47,92.88 47.88,92.88 47.69,93.07 ; 49.66,93.07 49.85,92.88 51.68,92.88 51.87,93.07 ; 49.66,93.07 R23.1 ; R22.2 46.25,93.07 46.44,92.88 47.5,92.88 47.69,93.07 ; 47.69,93.07 L2.4 ; 51.87,93.07 52.06,92.88 53.4,92.88 53.59,93.07 53.59,93.1 ; 51.87,93.07 R25.1 ; 53.59,93.1 53.82,92.88 56.2,92.88 56.67,93.34 56.67,95.7 U8.1 ; 53.59,93.1 R24.1
  TOP w1.168: U8.1 56.67,98.84 U6.1
CANH_2A: length 18.5
  TOP w1.168: JMP10.2 77.09,93.98 75.35,95.72 R18.2 C6.1 U9.1 62.4,95.72 62.39,95.71 U8.3
CANH_3: length 21.3
  TOP w0.191: 29.66,58.78 29.85,58.59 31.43,58.59 31.62,58.78 ; 29.66,58.78 L3.4 ; 29.66,58.78 29.47,58.59 28.52,58.59 28.22,58.9 R38.2 ; 31.62,58.78 31.81,58.59 33.64,58.59 33.83,58.78 ; 31.62,58.78 R39.1 ; U17.1 38.64,58.91 38.32,58.59 35.75,58.59 35.56,58.78 35.56,58.78 ; R41.1 33.83,58.78 ; 33.83,58.78 34.02,58.59 35.37,58.59 35.56,58.78 ; 35.56,58.78 R40.1
  TOP w1.168: U17.1 38.64,64.55 U15.1
CANH_3A: length 17.2
  TOP w1.168: U17.3 45.85,61.42 U18.1 C11.1 R34.2 58.73,60.15 JMP16.2
CANH_4: length 21.5
  TOP w0.191: R54.2 43.84,24.75 44.03,24.56 45.09,24.56 45.28,24.75 ; 51.18,24.79 51.18,24.75 50.99,24.56 49.64,24.56 49.45,24.75 ; 51.18,24.79 R56.1 ; 51.18,24.79 51.42,24.55 54.01,24.55 54.26,24.8 U25.1 ; 49.45,24.75 R57.1 ; 49.45,24.75 49.26,24.56 47.43,24.56 47.24,24.75 ; 47.24,24.75 R55.1 ; 47.24,24.75 47.05,24.56 45.47,24.56 45.28,24.75 ; 45.28,24.75 L4.4
  TOP w1.168: U25.1 54.26,30.51 U24.1
CANH_4A: length 19.7
  TOP w1.168: U25.3 U27.1 C16.1 R50.2 73.05,27.38 74.78,25.65 JMP22.2
CANH_SURGE1: length 12.3
  TOP w1.168: R4.1 P1.1
CANH_SURGE2: length 10.3
  TOP w1.168: R18.1 P3.1
CANH_SURGE3: length 11.6
  TOP w1.168: R34.1 P5.1
CANH_SURGE4: length 10.3
  TOP w1.168: R50.1 P7.1
CANL1: length 9.5
  TOP w0.191: 33.23,126.84 33.42,127.03 34.54,127.03 34.77,126.8 R10.1 34.77,123.22 U4.1 ; 33.23,126.84 L1.2 ; 33.23,126.84 33.04,127.03 30.52,127.03 30.33,126.84 U3.6
CANL2: length 9.6
  TOP w0.191: 43.14,92.3 L2.2 ; 43.14,92.3 42.95,92.49 40.43,92.49 40.24,92.3 U10.6 ; 43.14,92.3 43.14,92.3 43.33,92.49 44.58,92.49 44.68,92.39 R26.1 44.68,88.67 U12.1
CANL3: length 9.5
  TOP w0.191: 25.11,58.01 L3.2 ; 25.11,58.01 25.3,58.2 26.31,58.2 26.64,57.87 R42.1 26.64,54.38 U22.1 ; 25.11,58.01 24.92,58.2 22.39,58.2 22.2,58.01 U19.6
CANL4: length 9.6
  TOP w0.191: 40.73,23.97 40.54,24.16 38.01,24.16 37.82,23.97 U28.6 ; 40.73,23.97 L4.2 ; 40.73,23.97 40.73,23.97 40.92,24.16 42.01,24.16 42.27,23.9 R58.1 42.27,20.35 U30.1
CANL_1: length 27.8
  TOP w0.191: 43.69,126.84 43.88,127.03 47.02,127.03 47.31,126.75 U5.1 ; 43.69,126.84 43.5,127.03 42.15,127.03 41.96,126.84 41.96,126.84 ; 43.69,126.84 R11.2 ; 39.75,126.84 R12.1 ; 39.75,126.84 39.56,127.03 37.97,127.03 37.78,126.84 37.78,126.84 ; 39.75,126.84 39.75,126.84 39.94,127.03 41.77,127.03 41.96,126.84 ; 41.96,126.84 R9.2 ; 37.78,126.84 37.59,127.03 36.61,127.03 36.35,126.77 R10.2 ; 37.78,126.84 L1.3
  TOP w1.168: U5.1 47.32,126.16 C4.1 R14.1 58.24,126.16 JMP4.3
CANL_2: length 21.4
  TOP w0.191: 51.87,92.3 R25.2 ; 51.87,92.3 51.68,92.49 49.82,92.49 49.66,92.33 ; 51.87,92.3 52.06,92.49 53.4,92.49 53.59,92.3 53.59,92.25 ; R26.2 46.25,92.3 46.44,92.49 47.5,92.49 47.69,92.3 ; 47.69,92.3 L2.3 ; 47.69,92.3 47.88,92.49 49.5,92.49 49.66,92.33 ; 49.66,92.33 R28.1 ; 53.59,92.25 R27.2 ; 53.59,92.25 53.82,92.48 56.24,92.48 56.67,92.05 56.67,89.67 U13.1
  TOP w1.168: U14.1 56.67,86.42 U13.1
CANL_2A: length 18.5
  TOP w1.168: JMP10.3 77.22,91.44 75.43,89.65 R32.1 C9.1 U11.2 64.3,89.65 64.29,89.66 U13.3
CANL_3: length 21.4
  TOP w0.191: 33.83,58.01 33.83,58.02 33.66,58.2 31.8,58.2 31.62,58.02 ; 33.83,58.01 34.02,58.2 35.37,58.2 35.56,58.01 35.56,57.98 ; 33.83,58.01 R41.2 ; 31.62,58.02 R44.1 ; 31.62,58.02 31.45,58.2 29.85,58.2 29.66,58.01 ; L3.3 29.66,58.01 ; 29.66,58.01 29.47,58.2 28.52,58.2 28.22,57.89 R42.2 ; 35.56,57.98 35.78,58.19 38.33,58.19 38.64,57.88 U21.1 ; 35.56,57.98 R43.2
  TOP w1.168: U23.1 38.64,52.13 U21.1
CANL_3A: length 17.2
  TOP w1.168: JMP16.3 58.6,56.57 R48.1 C14.1 U20.2 45.92,55.37 U21.3
CANL_4: length 21.5
  TOP w0.191: L4.3 45.28,23.97 ; 45.28,23.97 45.09,24.16 44.03,24.16 43.84,23.97 R58.2 ; 45.28,23.97 45.47,24.16 47.05,24.16 47.24,23.97 47.24,23.97 ; 49.45,23.97 49.64,24.16 50.99,24.16 51.18,23.97 51.18,23.89 ; 49.45,23.97 R57.2 ; 49.45,23.97 49.26,24.16 47.43,24.16 47.24,23.97 ; 47.24,23.97 R60.1 ; 51.18,23.89 51.45,24.16 53.98,24.16 54.26,23.87 U31.1 ; 51.18,23.89 R59.2
  TOP w1.168: U32.1 54.26,18.09 U31.1
CANL_4A: length 19.8
  TOP w1.168: U31.3 U29.1 64.41,21.36 C20.1 R64.1 73,21.36 74.73,23.09 77.32,23.09 JMP22.3
CANL_SURGE1: length 12.4
  TOP w1.168: R14.2 P2.1
CANL_SURGE2: length 10.4
  TOP w1.168: R32.2 P4.1
CANL_SURGE3: length 11.6
  TOP w1.168: R48.2 P6.1
CANL_SURGE4: length 10.4
  TOP w1.168: R64.2 P8.1
PD1: length 2.3
  TOP w1.168: R2.1 JMP1.1
PD2: length 2.3
  TOP w1.168: R19.1 JMP7.1
PD3: length 2.3
  TOP w1.168: R35.1 JMP13.1
PD4: length 2.3
  TOP w1.168: R51.1 JMP19.1
PD_SC1: length 2.5
  TOP w1.168: R3.1 JMP1.3
PD_SC2: length 2.5
  TOP w1.168: R20.1 JMP7.3
PD_SC3: length 2.5
  TOP w1.168: R36.1 JMP13.3
PD_SC4: length 2.5
  TOP w1.168: R52.1 JMP19.3
PU1: length 2.8
  TOP w1.168: R1.2 JMP1.4
PU2: length 2.5
  TOP w1.168: R17.2 JMP7.4
PU3: length 2.3
  TOP w1.168: R33.2 JMP13.4
PU4: length 2.3
  TOP w1.168: R49.2 JMP19.4
RXD1: length 7.8
  TOP w1.168: U3.4 24.15,125.32 22.52,123.7 C5.1 R13.1 R15.2
RXD2: length 7.8
  TOP w1.168: U10.4 34.05,90.78 32.43,89.15 C10.1 R29.1 R30.2
RXD3: length 7.8
  TOP w1.168: R46.2 R45.1 C15.1 14.39,54.86 16.02,56.49 U19.4
RXD4: length 7.8
  TOP w1.168: R62.2 R61.1 C19.1 30.01,20.83 31.64,22.45 U28.4
RXD_SD1: length 4.3
  TOP w1.168: JMP6.2 R16.2 R15.1
RXD_SD2: length 4.3
  TOP w1.168: JMP12.2 R31.2 R30.1
RXD_SD3: length 4.3
  TOP w1.168: R46.1 R47.2 JMP18.2
RXD_SD4: length 4.3
  TOP w1.168: JMP24.2 R63.2 R62.1
SPLIT1: length 30.6
  TOP w0.508: C3.1 v1(42.18,123.2)
  TOP w1.168: R11.1 C3.1 ; R8.2 v1(42.16,129.54)
  BOTTOM w1.168: v1(42.16,129.54) 42.29,129.47 42.29,123.32 v1(42.18,123.2) 27.67,123.2 27.43,123.44 JMP5.1
SPLIT2: length 32.4
  TOP w0.508: C8.1 v1(52.08,88.66)
  TOP w1.168: R24.2 v1(53.59,96.39) ; R27.1 C8.1
  BOTTOM w1.168: JMP11.1 37.34,88.9 37.58,88.66 v1(52.08,88.66) 53.59,90.17 v1(53.59,96.39)
SPLIT3: length 32.4
  TOP w0.508: C13.1 v1(34.05,54.37)
  TOP w1.168: R40.2 v1(35.56,62.1) ; R43.1 C13.1
  BOTTOM w1.168: JMP17.1 19.3,54.61 19.55,54.37 v1(34.05,54.37) 35.56,55.88 v1(35.56,62.1)
SPLIT4: length 32.4
  TOP w0.508: C18.1 v1(49.67,20.33)
  TOP w1.168: R56.2 v1(51.18,28.07) ; R59.1 C18.1
  BOTTOM w1.168: v1(51.18,28.07) 51.18,21.84 v1(49.67,20.33) 35.17,20.33 34.92,20.57 JMP23.1
SPLIT/VIO1: length 11.2
  TOP w1.168: U3.5 30.33,125.32 30.33,117.47 29.18,116.33 JMP5.2
SPLIT/VIO2: length 11.4
  TOP w1.168: JMP11.2 39.41,81.79 40.24,82.61 U10.5
SPLIT/VIO3: length 11.4
  TOP w1.168: U19.5 22.2,48.32 21.37,47.5 JMP17.2
SPLIT/VIO4: length 11.4
  TOP w1.168: JMP23.2 37,13.46 37.82,14.29 U28.5
STB1: length 9.6
  TOP w1.168: JMP1.2 28.96,136.47 29.03,136.4 29.34,136.4 30.33,135.41 U3.8
STB2: length 9.6
  TOP w1.168: U10.8 40.24,100.86 39.24,101.85 38.94,101.85 38.86,101.93 JMP7.2
STB3: length 9.6
  TOP w1.168: U19.8 22.2,66.57 21.21,67.56 20.9,67.56 20.83,67.64 JMP13.2
STB4: length 9.6
  TOP w1.168: U28.8 37.82,32.54 36.83,33.53 36.53,33.53 36.45,33.6 JMP19.2
TXD1: length 13.6
  TOP w1.168: U3.1 24.15,129.13 22.6,130.68 R5.1 JMP3.2 JMP2.2
TXD2: length 13.6
  TOP w1.168: U10.1 34.05,94.59 32.5,96.14 R21.1 JMP9.2 JMP8.2
TXD3: length 13.6
  TOP w1.168: JMP14.2 JMP15.2 R37.1 14.47,61.85 16.02,60.3 U19.1
TXD4: length 13.6
  TOP w1.168: U28.1 31.64,26.26 30.09,27.81 19.94,27.81
VIO: length 217.6
  TOP w1.168: R33.1 v1(12.9,65.81) ; R45.2 v1(11.81,58.04) ; R1.1 v1(20.57,134.39) ; R17.1 v1(30.76,100.38) ; R61.2 v1(27.43,24) ; C30.2 JMP17.3 ; R29.2 v1(29.84,92.33) ; C29.2 JMP11.3 ; C31.2 JMP23.3 ; JMP5.3 C28.2 ; R49.1 v1(28.52,31.55) ; R13.2 v1(19.94,126.87)
  BOTTOM w1.168: 29.84,81.1 31.7,79.25 JMP11.3 ; 29.84,81.1 v1(29.84,92.33) 30.76,93.24 v1(30.76,100.38) 30.76,103.91 30.78,112.62 29.61,113.79 JMP5.3 22.07,113.79 19.94,115.93 v1(19.94,126.87) 20.57,127.51 v1(20.57,134.39) 20.57,138.84 20.58,140.59 26.29,146.3 JMP25.1 ; 29.84,81.1 27.48,78.74 19.05,78.74 12.9,72.59 v1(12.9,65.81) 12.9,59.13 v1(11.81,58.04) 11.81,47.98 14.83,44.96 JMP17.3 19.3,41.15 27.92,33.78 28.52,33.18 v1(28.52,31.55) 28.52,25.1 v1(27.43,24) 27.43,13.67 30.18,10.92 JMP23.3

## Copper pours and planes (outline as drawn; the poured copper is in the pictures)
GND on TOP: 0.64,0.64 0.64,176.53 88.9,176.53 88.9,0.64 ; 3 cut-outs
GND on BOTTOM, L2_GND: 0.64,176.53 88.9,176.53 88.9,0.64 0.64,0.64
VCC on TOP: 39.37,138.18 39.37,149.22 37.47,151.13 29.84,151.13 22.23,158.75 22.23,176.53 41.27,176.53 41.27,138.18
VCC on L3_PWR: 0.64,176.53 88.9,176.53 88.9,0.64 0.64,0.64

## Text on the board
BOTTOM: LAYER 4 - BOTTOM SIDE
Board Geometry/Soldermask Bottom: SOLDERMASK BOTTOM
Package Geometry/Pastemask Bottom: PASTEMASK BOTTOM
Ref Des/Silkscreen Bottom: SILKSCREEN BOTTOM
TOP: LAYER 1 - TOP SIDE | 6591689 | SURGE PROTECTED CAN
Board Geometry/Soldermask Top: SOLDERMASK TOP | 6591689 | SURGE PROTECTED CAN
Package Geometry/Pastemask Top: PASTEMASK TOP
Ref Des/Silkscreen Top: TXD | RXD | GND | PULLUP | SPLIT | VIO | PD 1 | PIN 8 | PD 2 | TVS | VCC | TBU | TISP | CANH | CANL | GDT | SILKSCREEN TOP
L2_GND: LAYER 2 - GND PLANE
L3_PWR: LAYER 3 - PWR PLANE
XSECTION_CHART: * AIR 0 MIL | * SOLDERMASK-0.8MIL 0.8 MIL | L1: COPPER_1/2OZ_PLATED 1.4 MIL | * CORE 35 MIL | L2: COPPER_1.0OZ 1.4 MIL | * FILL_0.150 5.91 MIL | L3: COPPER_1.0OZ 1.4 MIL | L4: COPPER_1/2OZ_PLATED 1.4 MIL | DESIGN CROSS SECTION CHART | ___________________________ | TOTAL THICKNESS 83.11 MIL | 1-4
DIMENSION: FABRICATION DRAWING | CAD ORIGIN
User.6: LAYER 1 | LAYER 2 | LAYER 3 | LAYER 4 | LAYER | NO. | TABLE 1: | TOP | L2_GND | L3_PWR | BOTTOM | NAME | DIFFIRENTIAL PAIR | IMPEDANCE (OHMS) | 120 +/- 10% | DIFF TRACE | WIDTH | 0.0075" | SPACING | 0.008" | SINGLE ENDED | 60 +/- 10% | TRACE WIDTH | 0.046" | REFERENCE | SPECIAL FAB NOTES: | PLACE DRILL CHART HERE: | 1:FAB SHOP MUST FOLLOW THE SOLDER MASK REVIEW LAYERS. | 2: | MIN. ANNULAR RING 2 MIL EXTERNAL PER IPC-6012C CLASS 2 | REGISTRATION TOLERANCES: METAL +/- X MIL,HOLES +/- X MIL | IMPEDANCE CONTROL: | BOARD SIZE (REFER ALSO ARRAY/PANEL PROFILING INFORMATION) | MIXED DIELECTRIC: | LAMINATE MATERIAL: | THICKNESS: | TOLERANCE: | COPPER THICKNESS (FINISHED): | BOARD FINISH: | NUMBER OF LAYERS: | MIN. TRACK WIDTH: | MIN. CLEARANCE  : | MIN. VIA PAD/DRILL: | THIEVING ALLOWED: | X | OUTER: | INNER SIGNAL: | INNER PLANE: | OTHER: | SILKSCREEN: | SOLDERMASK: (PER IPC-6011,6012) | BOARD SURFACE TREATMENT: | ADDITIONAL REQUIREMENTS: | VENDOR MARKING: | SILKSCREEN COLOR: | SOLDERMASK COLOR: | THROUGH-HOLE VIA TREATMENT: | VIA FILL USING NON-CONDUCTIVE EPOXY: | FOR WIRE BONDING: | VENDOR DATE CODE,UL,LOGO: | FR-4 HIGH Tg | 0.062" +/-10% | IPC-6012C TYPE 3 CLASS 2 | OTHER +/- | MICRO-SECTION | CERTIFICATES OF COMPLIANCE | NICKEL/GOLD (ENIG) | IMMERSION TIN | HARD GOLD | IN AN OPEN AREA | 1/4 OZ. | OPEN | NO | 4 | 7.5MIL | 5.0 MIL | 20/10 MIL | NONE | DESIGN INFORMATION | ROGERS 4350B | 0.093" +/-10% | YES | TDR REPORTS/COUPONS | WHITE | GREEN | SOFT GOLD | TENTED | 1/2 OZ. | BOW & TWIST: | ORGANIC (OSP) | OTHER | WHERE INDICATED (SEE DRAWING) | YES - SEE TABLE 1 | ETCH | IDENTIFIER: | BLUE | RoHS | 1.0 OZ. | SILKSCREEN | PER SUPPLIED ARTWORK | ALL 10 MIL VIAS | ALL x MIL VIAS | ELECTRICAL TEST | UL 94V-0 | 0.083" +/-10% | HASL | 2.0 OZ. | BREAK-AWAY | ENEPIG
User.10: FIGURE | SIZE | 255.0 | 46.0 | 38.0 | 10.0 | 125.0 | DRILL CHART: TOP to BOTTOM | ALL UNITS ARE IN MILS | TOLERANCE | +5.0/-5.0 | +3.0/-3.0 | +2.0/-2.0 | PLATED | NON-PLATED | QTY | 10 | 4 | 74 | 410
